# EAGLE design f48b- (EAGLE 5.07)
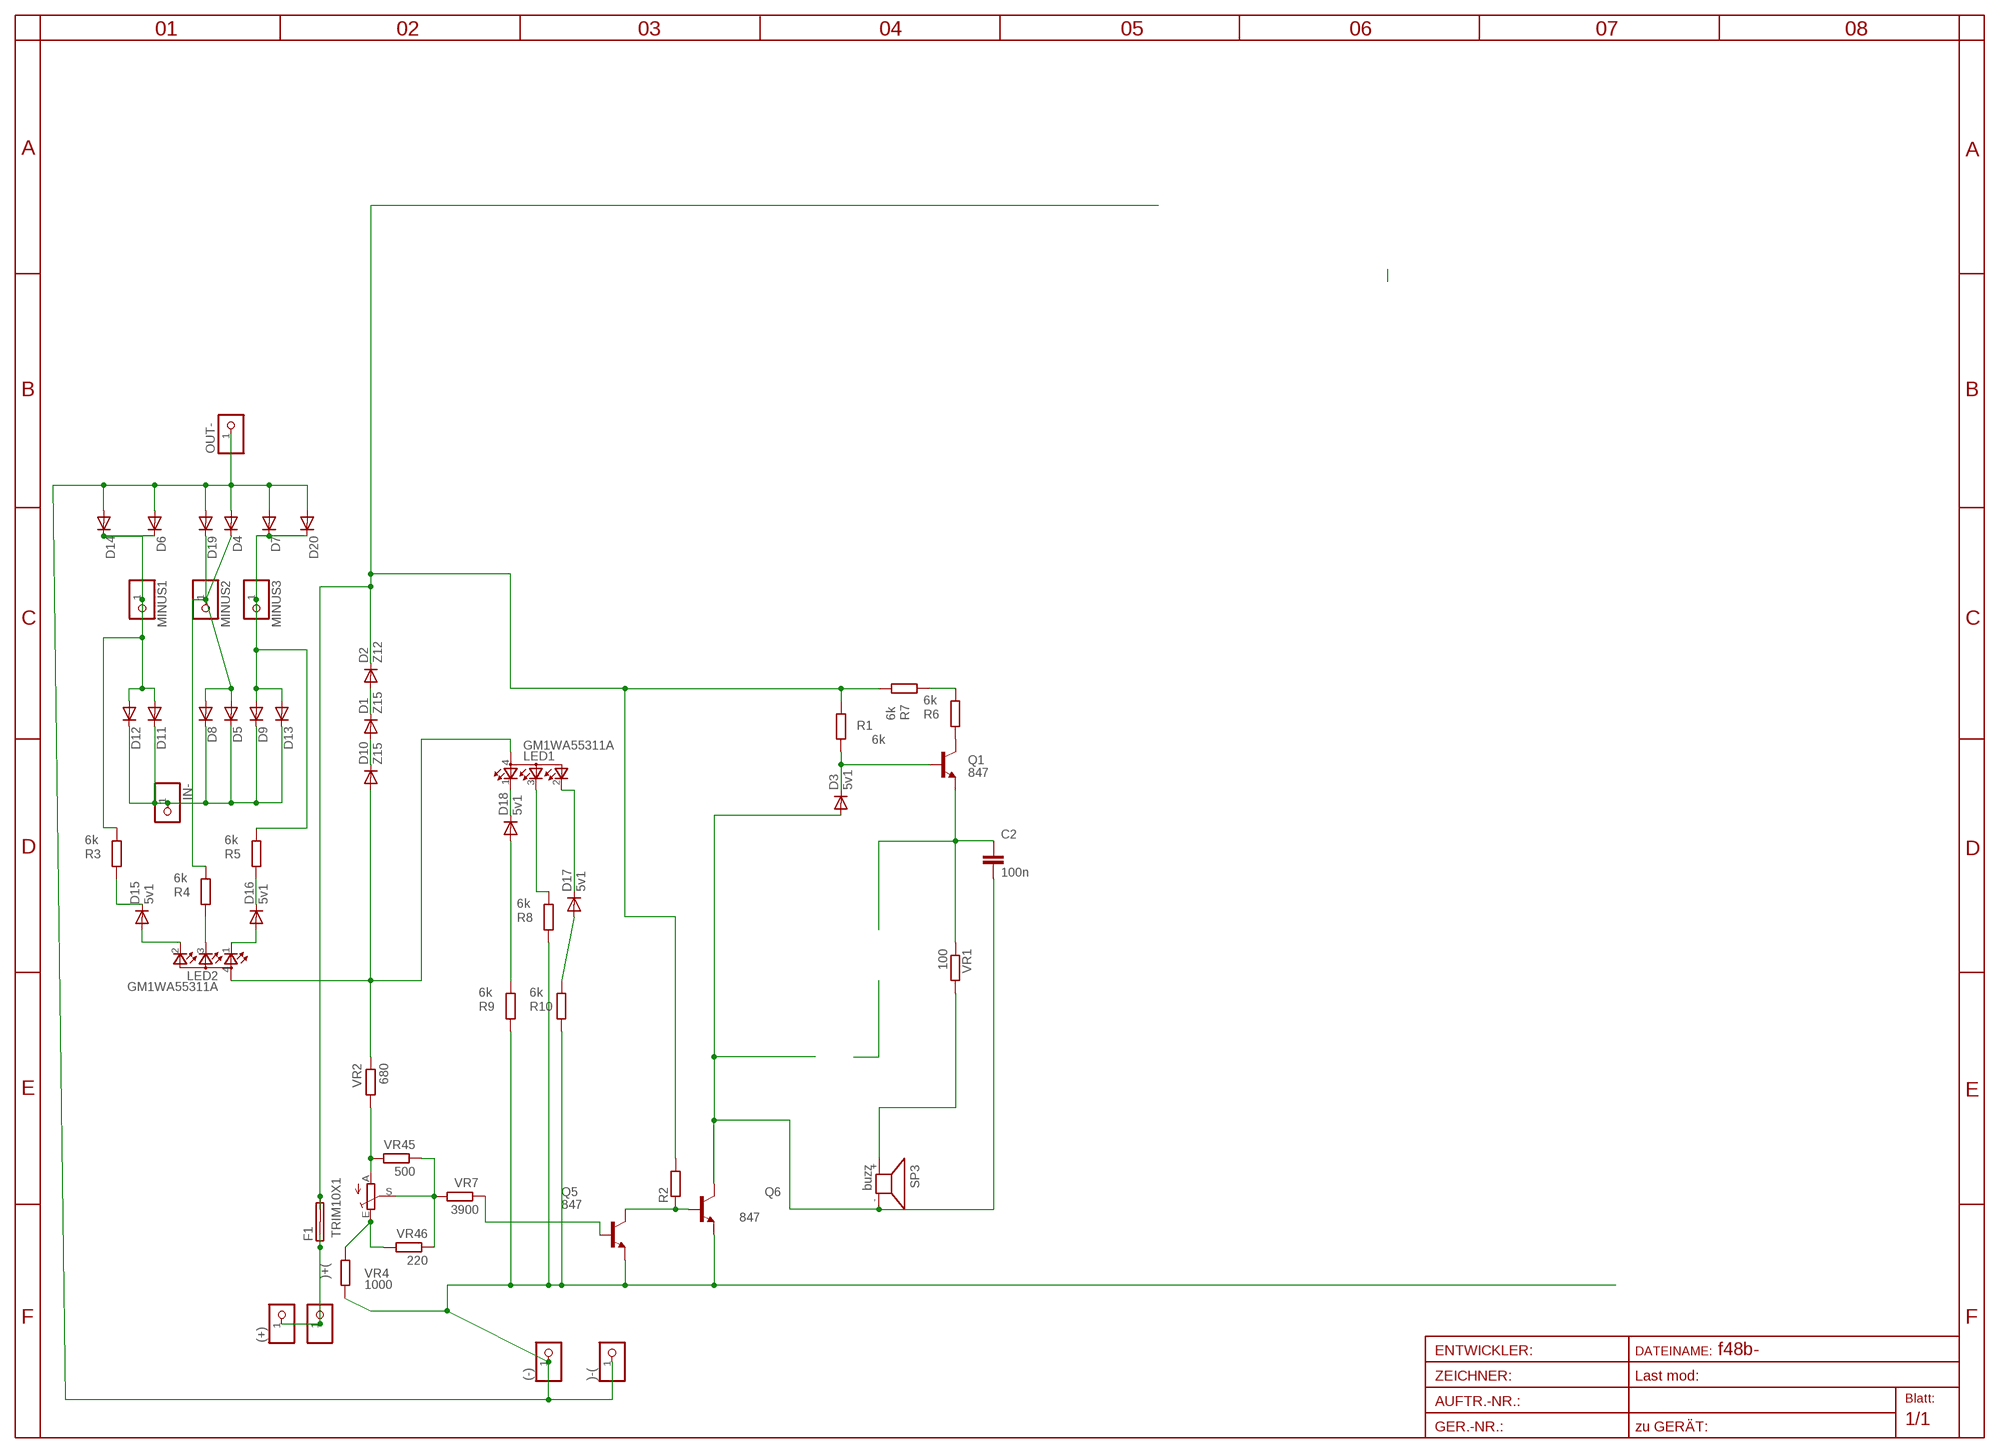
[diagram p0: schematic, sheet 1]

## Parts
(+)  PINHD-1X14.5MM  [1X4MM5]
(-)  PINHD-1X14.5MM  [1X4MM5]
)+(  PINHD-1X11X0.4  [1X01]
)-(  PINHD-1X11X0.4  [1X01]
C2  100n  C-EUC1206  [C1206]
D1  Z15  DIODE-MINIMELF  [MINIMELF]
D2  Z12  DIODE-MINIMELF  [MINIMELF]
D3  5v1  DIODE-MINIMELF  [MINIMELF]
D4  DIODE-SMC  [SMC]
D5  DIODE-SMC  [SMC]
D6  DIODE-SMC  [SMC]
D7  DIODE-SMC  [SMC]
D8  DIODE-SMC  [SMC]
D9  DIODE-SMC  [SMC]
D10  Z15  DIODE-MINIMELF  [MINIMELF]
D11  DIODE-SMC  [SMC]
D12  DIODE-SMC  [SMC]
D13  DIODE-SMC  [SMC]
D14  DIODE-SMC  [SMC]
D15  5v1  DIODE-MINIMELF  [MINIMELF]
D16  5v1  DIODE-MINIMELF  [MINIMELF]
D17  5v1  DIODE-MINIMELF  [MINIMELF]
D18  5v1  DIODE-MINIMELF  [MINIMELF]
D19  DIODE-SMC  [SMC]
D20  DIODE-SMC  [SMC]
F1  SHK20L7MM5  [7MM5]
IN-  PINHD-1X12MM3  [1X2MM3]
LED1  GM1WA55311A  [FULL3528]
LED2  GM1WA55311A  [FULL3528]
MINUS1  PINHD-1X12MM3  [1X2MM3]
MINUS2  PINHD-1X12MM3  [1X2MM3]
MINUS3  PINHD-1X12MM3  [1X2MM3]
OUT-  PINHD-1X12MM3  [1X2MM3]
Q1  847  BC847CSMD  [SOT23]
Q5  847  BC847CSMD  [SOT23]
Q6  847  BC847CSMD  [SOT23]
R1  6k  R-EU_R1206  [R1206]
R2  R-EU_R1206  [R1206]
R3  6k  R-EU_R1206  [R1206]
R4  6k  R-EU_0207/20  [0207/20]
R5  6k  R-EU_0207/25  [0207/25]
R6  6k  R-EU_R1206  [R1206]
R7  6k  R-EU_R1206  [R1206]
R8  6k  R-EU_R0805  [R0805]
R9  6k  R-EU_R0805  [R0805]
R10  6k  R-EU_R0805  [R0805]
SP3  buzz  KSS12017MM  [KSS1202]
TRIM10X1  TRIM_EU-S64W  [S64W]
VR1  100  R-EU_R0805  [R0805]
VR2  680  R-EU_R0805  [R0805]
VR4  1000  R-EU_R0805  [R0805]
VR7  3900  R-EU_R0805  [R0805]
VR45  500  R-EU_R0805  [R0805]
VR46  220  R-EU_R0805  [R0805]

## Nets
B1: D6.C D11.A D12.A D14.C MINUS1.1 R3.1
B2: D7.C D9.A D13.A D20.C MINUS3.1 R5.1
B3: D4.C D5.A D8.A D19.C MINUS2.1 R4.1
BUZ-: C2.2 D3.A Q6.3(C) SP3.-
BUZZ+: SP3.+ VR1.2
FPLUS: D2.C F1.2A F1.2B R1.2 R2.2 R7.1
IN+: (+).1 )+(.1 F1.1A F1.1B
IN-: D5.C D8.C D9.C D11.C D12.C D13.C IN-.1
N$1: D1.C D2.A
N$2: D3.C Q1.1(B) R1.1
N$3: Q5.3(C) Q6.1(B) R2.1
N$4: D1.A D10.C
N$6: Q1.3(C) R6.2
N$7: TRIM10X1.A VR2.2 VR45.2
N$8: C2.1 Q1.2(E) VR1.1
N$9: D16.A LED2.1(CRED)
N$10: D10.A LED1.4(A) LED2.4(A) VR2.1
N$11: LED1.3(CBLUE) R8.1
N$12: D17.C LED1.2(CGREEN)
N$13: D15.C R3.2
N$14: D18.C LED1.1(CRED)
N$15: D15.A LED2.2(CGREEN)
N$16: LED2.3(CBLUE) R4.2
N$18: R6.1 R7.2
N$19: D16.C R5.2
N$22: TRIM10X1.S VR7.2 VR45.1 VR46.1
N$24: TRIM10X1.E VR4.1 VR46.2
N$26: D18.A R9.1
N$27: D17.A R10.1
N$168: Q5.1(B) VR7.1
OUT-: (-).1 )-(.1 D4.A D6.A D7.A D14.A D19.A D20.A OUT-.1 Q5.2(E) Q6.2(E) R8.2 R9.2 R10.2 VR4.2

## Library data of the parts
(+) (-) )+( )-( IN- MINUS1-MINUS3 OUT- = pinhead:PINHD-1X1: PIN HEADER
C2 = rcl:C-EU: CAPACITOR, European symbol
D1-D20 = diode:DIODE-: DIODE
F1 = fuse:SHK20L: FUSE HOLDER 5 x 20 mm, SH contact, SHH1 Schukat, E1073 Buerklin
LED1 LED2 = led:GM1WA55311A: Chip LED RGB Source: http://document.sharpsma.com/files/GM1WA55311A_SS.pdf
Q1 Q5 Q6 = transistor-npn:BC847*: NPN Transistor
R1 R3-R10 VR1 VR2 VR4 VR7 VR45 VR46 = rcl-2:R-EU_: RESISTOR, European symbol
R2 = rcl:R-EU_: RESISTOR, European symbol
SP3 = buzzer:KSS1201: SPEAKER
TRIM10X1 = pot:TRIM_EU-: POTENTIOMETER

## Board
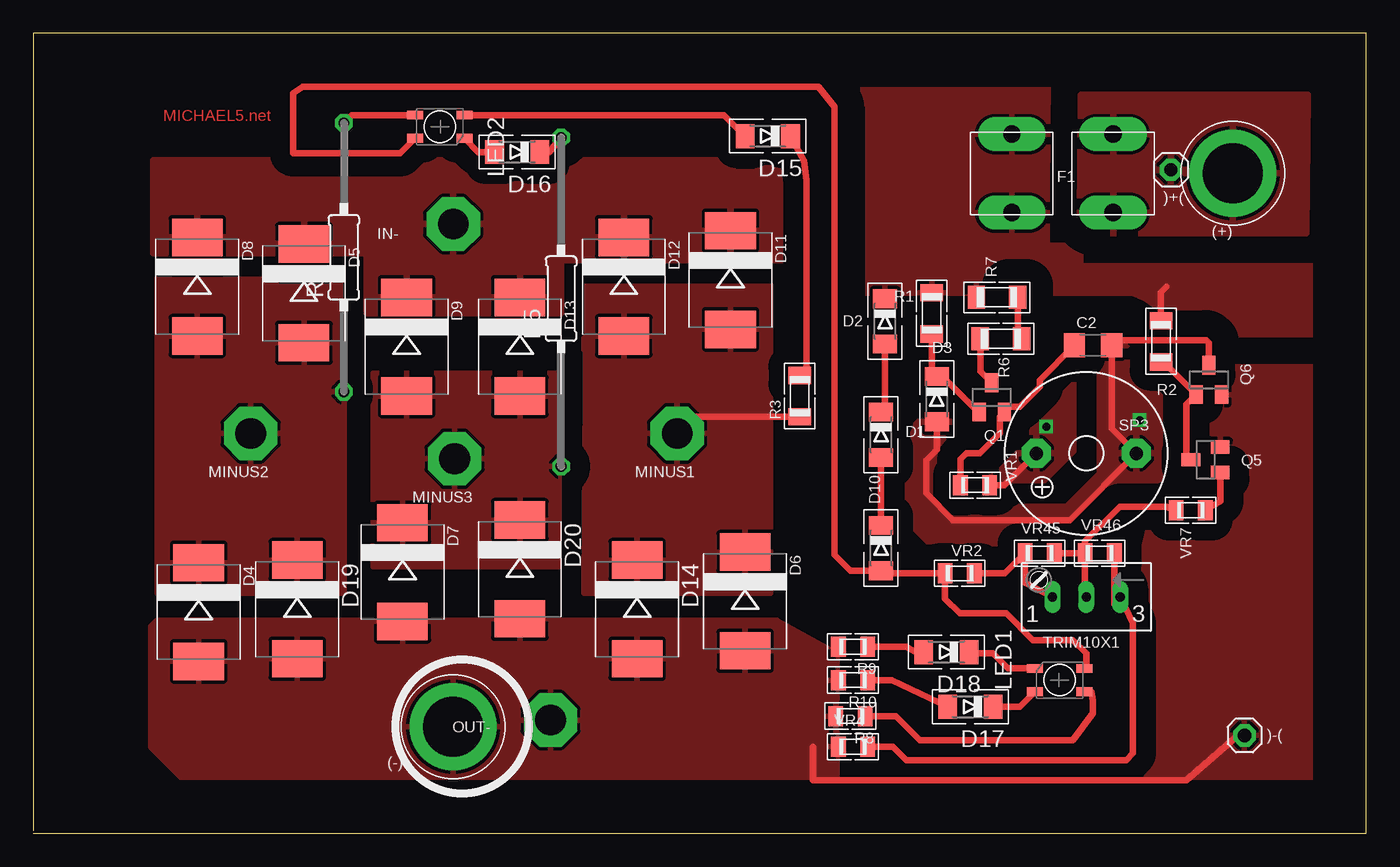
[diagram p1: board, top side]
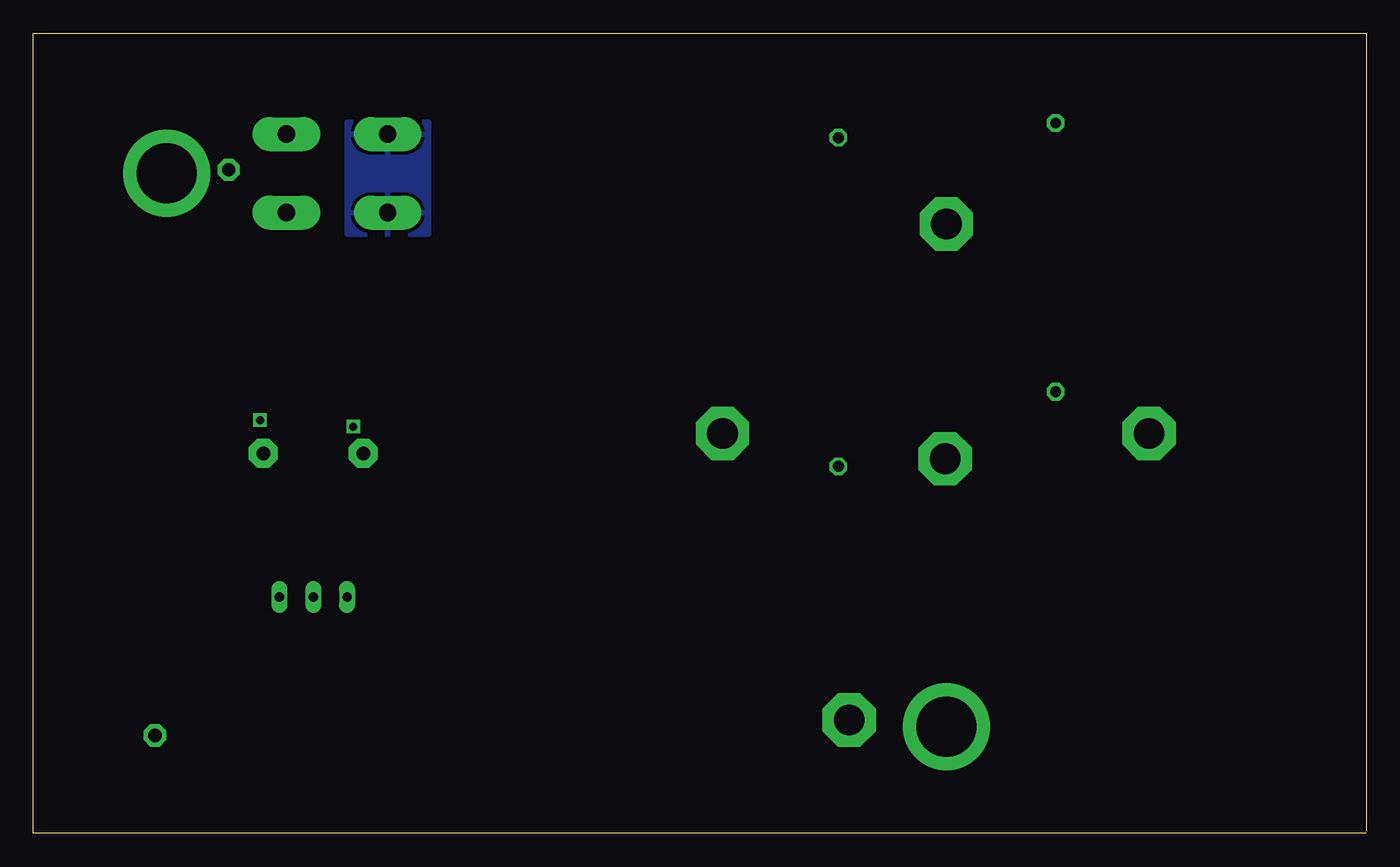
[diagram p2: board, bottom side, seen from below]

Size 100 x 60 mm. Coordinates in mm from the lower left corner, seen from the top.
Outline: 0,0 100,0 100,60 0,60 0,0.2
Copper layers (1*16): Top 0.035mm / dielectric 1.5mm / Bottom 0.035mm
Design rules "default *": minimum track width 8mil, minimum drill 4mil, track to track 8mil, track to pad 8mil, pad to pad 8mil, via to via 8mil, smd to smd 8mil, copper to edge 4mm, drill to drill 8mil, minimum pad ring 10mil, minimum via ring 8mil, stop-mask expansion 4mil, vias tented up to drill 0mil, thermal gap 10mil

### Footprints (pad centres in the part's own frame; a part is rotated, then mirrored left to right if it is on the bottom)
1X4MM5 = drill 4.5 pad 6.35 round: 1 0,0
1X01 = drill 1 pad 1.676 octagon: 1 0,0
C1206 = smd 1.6 x 1.8: 1 -1.4,0; 2 1.4,0
MINIMELF = smd 1.4 x 1.8: A 1.7,0; C -1.7,0
SMC = smd 2.8 x 3.8: A 3.7,0; C -3.7,0
7MM5 = drill 1.3 pad 2.54 long: 1A -3.8,2.94; 1B -3.8,-2.94; 2A 3.8,2.94; 2B 3.8,-2.94
1X2MM3 = drill 2.3 pad 4 octagon: 1 0,0
FULL3528 = smd 0.65 x 1.2: 1 0.875,1.85; 2 -0.875,1.85; 3 -0.875,-1.85; 4 0.875,-1.85
SOT23 = smd 1 x 1.4: 1 -0.95,-1.1; 2 0.95,-1.1; 3 0,1.1
R1206 = smd 1.3 x 1.7: 1 -1.55,0; 2 1.55,0
0207/20 = drill 0.813 octagon: 1 -10.08,0; 2 10.08,0
0207/25 = drill 0.813 octagon: 1 -12.58,0; 2 12.08,0
R0805 = smd 1.1 x 1.5: 1 -1.1,0; 2 1.1,0
KSS1202 = drill 1 pad 2.159 octagon: + 3.75,0; - -3.75,0
S64W = drill 0.7 long: A 2.54,1.27; E -2.54,1.27; S 0,1.27

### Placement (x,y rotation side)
(+)  90,49.5 0 top
(-)  31.5,8 0 top
)+(  85.34,49.77 0 top
)-(  90.87,7.35 0 top
C2  79.5,36.6 0 top
D1  63.6,29.9 270 top
D2  63.9,38.4 270 top
D3  67.78,32.57 270 top
D4  12.4,16.6 270 top
D5  20.3,40.5 270 top
D6  53.4,17.4 270 top
D7  27.7,19.6 270 top
D8  12.3,41 270 top
D9  28,36.5 270 top
D10  63.6,21.4 270 top
D11  52.3,41.5 270 top
D12  44.3,41 270 top
D13  36.5,36.5 270 top
D14  45.3,16.8 270 top
D15  55.1,52.3 180 top
D16  36.3,51.1 180 top
D17  70.3,9.5 180 top
D18  68.5,13.6 180 top
D19  19.8,16.8 270 top
D20  36.5,19.8 270 top
F1  77.22,49.5 180 top
IN-  31.5,45.7 180 top
LED1  77,11.5 90 top
LED2  30.5,53 270 top
MINUS1  48.3,30 180 top
MINUS2  16.3,30 180 top
MINUS3  31.6,28.1 180 top
OUT-  38.8,8.5 180 top
Q1  71.9,32.7 0 top
Q5  87.95,28.02 90 top
Q6  88.2,34.01 0 top
R1  67.4,39 90 top
R2  84.6,36.9 90 top
R3  57.5,32.8 90 top
R4  23.3,43.2 90 top
R5  39.6,40.1 90 top
R6  72.6,37.1 180 top
R7  72.3,40.2 0 top
R8  61.3,8.8 180 top
R9  61.5,14 180 top
R10  61.5,11.5 180 top
SP3  79,28.5 180 top
TRIM10X1  79,19 180 top
VR1  70.66,26.11 0 top
VR2  69.5,19.5 0 top
VR4  61.5,6.5 180 top
VR7  86.83,24.23 180 top
VR45  75.5,21 180 top
VR46  80,21 0 top

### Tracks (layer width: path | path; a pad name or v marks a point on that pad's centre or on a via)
B1
  Top 0.5: R3.1 49.55,31.25 MINUS1.1
  pour Top (isolate 1.5, rank 4): 55.3,18 41.3,18 41.3,42 55.3,42
B2
  pour Top (isolate 1.5, rank 3): 25.5,20 25.5,34.5 39.5,34.5 39.4,20
B3
  pour Top (isolate 1.5, rank 4): 9.3,18 9.3,42 23.3,42 23.3,18
BUZ-  (via drill 0.6)
  Top 0.5: Q6.3 88.2,36.8 88,37 81.3,37 C2.2 80.9,30.35 SP3.- 77.75,23.5 69,23.5 67,25.5 67,28 67.78,28.79 D3.A
  other vias: 83,31
  pour Top (isolate 1.5): 81.5,37.5 81.5,37 84.5,34 84.5,25.5 83.5,24.5 81,24.5 79,22.5 73.5,22.5 72.5,21.5 67.5,21.5 65.5,23.5 65.5,30 66.5,31 69,31 69,26 70.5,24.5 77.5,24.5 80,27 80,35
BUZZ+  (via drill 0.6)
  Top 0.5: VR1.2 72.86,26.11 SP3.+
  other vias: 76,30.5
  pour Top (isolate 1.5, rank 2): 77.5,35 78.5,34 78.5,26 77.5,25 72,25 71.5,25.5 71.5,30 72,30.5
FPLUS
  Top 0.5: R2.2 84.6,40.6 85,41
  pour Top (isolate 2, rank 3): 61.5,56.03 77,56.03 77,45 80.5,45 84.5,43.5 91,43.5 97,42.5 96.65,35.24 86,35.24 86,36.5 arc60 82.5,40.5 61.56,40.5 61.5,44.5
  pour Bottom (isolate 1.5, rank 4): 70.36,53.33 76.45,53.33 76.45,44.94 70.36,44.94
IN+
  pour Top (isolate 1.5): 78.6,55.4 95.6,55.4 95.5,45 79.5,45 78.5,46
IN-
  pour Top (isolate 1.5): 9,50.5 57,50.5 57,43 39.6,43 39.6,39 25,39 25,43.5 9,43.5
N$1
  Top 0.5: D2.A 63.9,31.9 D1.C
N$2
  Top 0.5: Q1.1 70.9,31.6 68.5,34 68.06,34 D3.C 67.4,34.65 R1.1
N$3
  Top 0.5: Q5.3 86.85,28.15 86.5,28.5 86.5,32.16 Q6.1 84.81,35.35 R2.1
N$4
  Top 0.5: D10.C D1.A
N$6
  Top 0.5: R6.2 71.05,34.65 Q1.3
N$7
  Top 0.5: VR2.2 72.9,19.5 VR45.2 74.4,18.79 TRIM10X1.A
N$8
  Top 0.5: VR1.1 69.56,28.06 70,28.5 71,28.5 72.5,30 72.5,31.25 Q1.2 73.25,32 74,32 75.5,33.5 75.5,34 C2.1
N$9
  Top 0.5: D16.A 33.38,51.1 LED2.1
N$10
  Top 0.5: LED2.4 27.52,51 19.5,51 19.5,55.5 20.2,56 58.9,56 60.1,54.5 60.1,20.9 61.3,19.7 D10.A 63.8,19.5 VR2.1 68.4,17.6 69.5,16.5 73,16.5 75,14.5 78,14.5 79,13.5 79,12.53 LED1.4
N$11
  Top 0.5: R8.1 64.7,8.8 66.5,7 78,7 79.5,9 79.5,10 79.38,10.62 LED1.3
N$12
  Top 0.5: D17.C 74.03,9.5 LED1.2
N$13
  Top 0.5: D15.C 57.8,50.45 58,49 58,39 58,34.35 R3.2
N$14
  Top 0.5: LED1.1 73.12,12.38 72,13.5 70.3,13.5 D18.C
N$15
  Top 0.5: LED2.2 51.83,53.88 D15.A
N$16
  Top 0.5: LED2.3 23.89,53.88 R4.2
N$18
  Top 0.5: R7.2 73.85,37.4 R6.1
N$19
  Top 0.5: D16.C 38.68,51.1 R5.2
N$22
  Top 0.5: VR46.1 VR45.1 | VR46.1 78.9,16.83 TRIM10X1.S | VR46.1 78.9,21.9 81.5,24.5 85.01,24.5 VR7.2
N$24
  Top 0.5: VR4.1 64.5,6.5 65.5,5.5 82,5.5 82.5,6 82.5,15.77 TRIM10X1.E 81.1,17.17 VR46.2
N$26
  Top 0.5: R9.1 65.5,14 66.5,13.4 D18.A
N$27
  Top 0.5: R10.1 64.4,11.5 D17.A
N$168
  Top 0.5: Q5.1 89.05,24.89 VR7.1
OUT-
  Top 0.5: 58.5,6.5 58.5,4 86.5,4 90.17,7.17 90.35,7.35 )-(.1
  pour Top (isolate 1.5, rank 2): 80.1,8.2 86.6,35 96.3,35 96.3,4.1 80.4,3.7
  pour Top (isolate 1.422, rank 4): 60.3,3.5 11.8,3.5 8.8,6.5 8.8,15.5 9.3,16 55.8,16 60.3,13.5

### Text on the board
Top: MICHAEL5.net
tTest: 4v4
Document: 1m | 10u | 10u | 300u | 2mA | 500u | 1m | 2m | 300u | 300u | 30u | 5m | 14m | 12m | 500u | 5m | 5m | 5m | 5m | 5m | 5m | 40m | 40m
